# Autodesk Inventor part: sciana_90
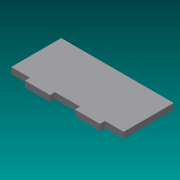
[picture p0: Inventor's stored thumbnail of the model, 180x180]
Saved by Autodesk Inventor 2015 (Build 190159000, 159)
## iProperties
Created: 2016-02
Part Number: sciana_90
Material: Generic
Document SubType Name: Modeling
Designer: Rafał
Density: 1 g/cm^3
Appearance: Default
Author: Rafał
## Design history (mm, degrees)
sketch "Sketch1"
  geometry: L1 (0, 0)-(-90, 0); L2 (-90, 0)-(-90, 40); L3 (-90, 40)-(0, 40); L4 (0, 40)-(0, 0); L5 (-15, 0)-(-35, 0); L6 (-35, 0)-(-35, -4); L7 (-35, -4)-(-15, -4); L8 (-15, -4)-(-15, 0); L9 (-75, 0)-(-55, 0); L10 (-55, 0)-(-55, -4); L11 (-55, -4)-(-75, -4); L12 (-75, -4)-(-75, 0)
  constraints: 24 end point, 6 parallel, 3 horizontal, 3 perpendicular, 2 point on line
  dimensions: "d0" = 90 distance of L2.end L3.end; "d1" = 40 distance of L1.end L2.end; "d2" = 20 distance of L7.end L6.end; "d3" = 4 distance of L6.end L5.end; "d4" = 15 distance between parallel lines of L4 L8; "d5" = 20 distance of L10.end L11.end; "d6" = 15 distance between parallel lines of L12 L2
extrude "Extrusion1" new body sketch "Sketch1" distance "d7" = 5; taper "d8" = 0 deg
body "Solid1"
